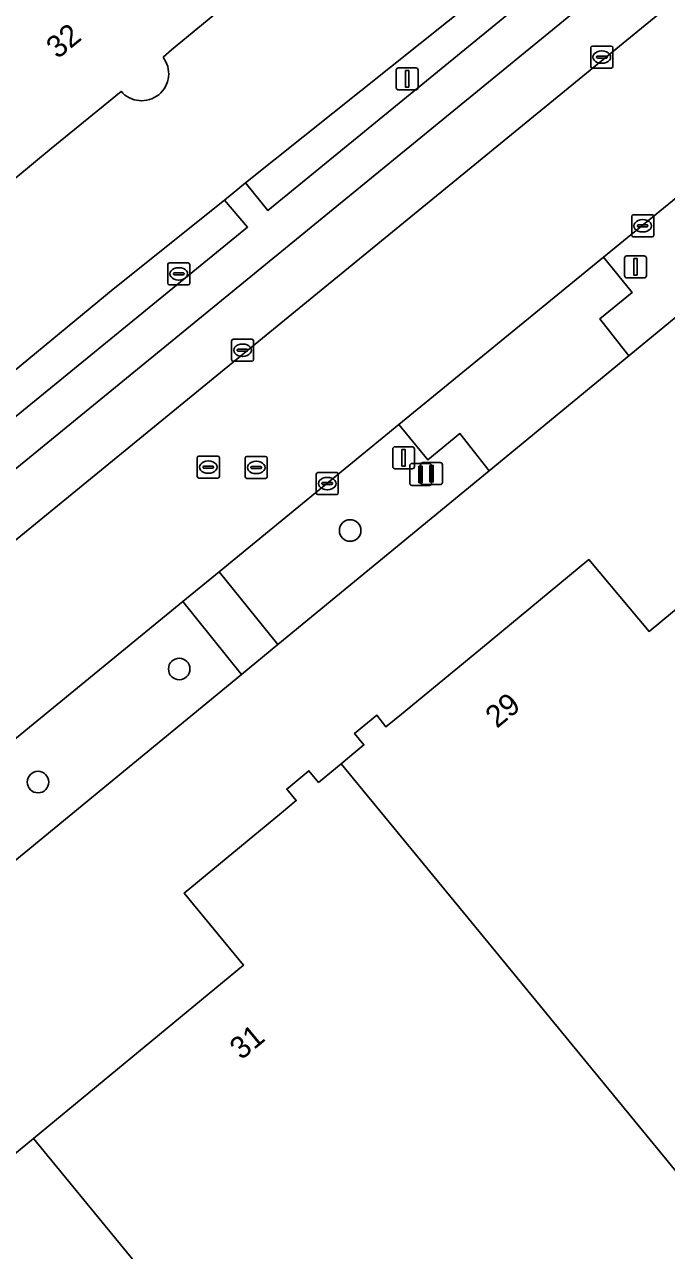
# Model space of a CAD drawing. Extents: x 156702 to 158052, y 387630 to 388992.
# Drawn here: x 156979.3 to 157008.5, y 388172.3 to 388228 of the extents above; entities that cross this region are included whole.
import ezdxf

# ---------------------------------------------------------------- set-up
doc = ezdxf.new("R2010")
doc.units = 0
for name, color, linetype in [('IMGEO_Afsluitpaal', 7, 'Continuous'), ('IMGEO_Berm_groen', 7, 'Continuous'), ('IMGEO_Boom', 7, 'Continuous'), ('IMGEO_Brandkraan', 7, 'Continuous'), ('IMGEO_Erf', 7, 'Continuous'), ('IMGEO_Groenvoorziening', 7, 'Continuous'), ('IMGEO_Hek', 7, 'Continuous'), ('IMGEO_Kolk', 7, 'Continuous'), ('IMGEO_Lichtmast', 7, 'Continuous'), ('IMGEO_Pand', 7, 'Continuous'), ('IMGEO_Pand_nummerreeks', 7, 'Continuous'), ('IMGEO_Parkeervlak_open', 7, 'Continuous'), ('IMGEO_Rijbaan_lokaal_gesloten', 7, 'Continuous'), ('IMGEO_Rijbaan_lokaal_open', 7, 'Continuous'), ('IMGEO_Rioolput', 7, 'Continuous'), ('IMGEO_Verkeersbordpaal', 7, 'Continuous'), ('IMGEO_Voetpad_open', 7, 'Continuous')]:
    doc.layers.add(name, color=color, linetype=linetype)

msp = doc.modelspace()

# ---------------------------------------------------------------- linework, layer by layer
at = {"layer": 'IMGEO_Afsluitpaal'}
for p, q in [((157006.554, 388216.563), (157006.554, 388217.363)), ((157006.554, 388217.363), (157006.554, 388216.563)), ((157006.654, 388217.463), (157007.444, 388217.463)), ((157007.444, 388217.463), (157006.654, 388217.463)), ((157007.544, 388217.363), (157007.544, 388216.563)), ((157007.544, 388216.563), (157007.544, 388217.363)), ((157007.444, 388216.463), (157006.654, 388216.463)), ((157006.654, 388216.463), (157007.444, 388216.463)), ((156996.014, 388207.884), (156996.014, 388208.684)), ((156996.014, 388208.684), (156996.014, 388207.884)), ((156996.114, 388208.784), (156996.904, 388208.784)), ((156996.904, 388208.784), (156996.114, 388208.784)), ((156997.004, 388208.684), (156997.004, 388207.884)), ((156997.004, 388207.884), (156997.004, 388208.684)), ((156996.904, 388207.784), (156996.114, 388207.784)), ((156996.114, 388207.784), (156996.904, 388207.784)), ((156997.285, 388207.165), (156997.285, 388207.965)), ((156997.285, 388207.965), (156997.285, 388207.165)), ((156997.385, 388208.065), (156998.175, 388208.065)), ((156998.175, 388208.065), (156997.385, 388208.065)), ((156998.275, 388207.965), (156998.275, 388207.165)), ((156998.275, 388207.165), (156998.275, 388207.965)), ((156998.175, 388207.065), (156997.385, 388207.065)), ((156997.385, 388207.065), (156998.175, 388207.065))]:
    msp.add_line(p, q, dxfattribs=at)
for points in [[(157006.974, 388217.338), (157007.124, 388217.338), (157007.124, 388216.588), (157006.974, 388216.588), (157006.974, 388217.338)], [(156996.434, 388208.659), (156996.584, 388208.659), (156996.584, 388207.909), (156996.434, 388207.909), (156996.434, 388208.659)], [(156997.705, 388207.94), (156997.855, 388207.94), (156997.855, 388207.19), (156997.705, 388207.19), (156997.705, 388207.94)]]:
    msp.add_lwpolyline(points, dxfattribs=at)
for centre, start, end in [((157006.654, 388217.363), 90, 180), ((157006.654, 388217.363), 90, 180), ((157007.444, 388217.363), 0, 90), ((157007.444, 388217.363), 360, 90), ((157006.654, 388216.563), 180, 270), ((157006.654, 388216.563), 180, 270), ((157007.444, 388216.563), 270, 0), ((157007.444, 388216.563), 270, 0), ((156996.114, 388208.684), 90, 180), ((156996.114, 388208.684), 90, 180), ((156996.904, 388208.684), 0, 90), ((156996.904, 388208.684), 360, 90), ((156996.114, 388207.884), 180, 270), ((156996.114, 388207.884), 180, 270), ((156996.904, 388207.884), 270, 0), ((156996.904, 388207.884), 270, 0), ((156997.385, 388207.965), 90, 180), ((156997.385, 388207.965), 90, 180), ((156998.175, 388207.965), 0, 90), ((156998.175, 388207.965), 360, 90), ((156997.385, 388207.165), 180, 270), ((156997.385, 388207.165), 180, 270), ((156998.175, 388207.165), 270, 0), ((156998.175, 388207.165), 270, 0)]:
    msp.add_arc(centre, 0.1, start, end, dxfattribs=at)
at = {"layer": 'IMGEO_Berm_groen'}
for points in [[(157019.353, 388223.29), (157018.081, 388224.919), (157016.583, 388223.743), (157015.343, 388225.354), (157005.603, 388217.405), (157006.895, 388215.796), (157005.431, 388214.601), (157006.748, 388212.913), (157010.188, 388215.745)], [(157000.402, 388207.692), (156999.068, 388209.388), (156997.608, 388208.193), (156996.295, 388209.802), (156988.13, 388203.105), (156990.785, 388199.795)], [(156989.145, 388198.44), (156986.467, 388201.756), (156976.878, 388193.907), (156978.236, 388192.321), (156976.749, 388191.123), (156978.144, 388189.413)]]:
    msp.add_lwpolyline(points, close=True, dxfattribs=at)
at = {"layer": 'IMGEO_Boom'}
for centre in [(156994.079, 388204.98), (156986.31, 388198.686), (156979.891, 388193.546)]:
    msp.add_circle(centre, 0.489, dxfattribs=at)
at = {"layer": 'IMGEO_Brandkraan'}
for p, q in [((156985.789, 388216.218), (156985.789, 388217.07)), ((156985.864, 388217.144), (156986.716, 388217.144)), ((156986.79, 388217.07), (156986.79, 388216.218)), ((156986.048, 388216.638), (156986.048, 388216.65)), ((156986.486, 388216.601), (156986.088, 388216.601)), ((156986.091, 388216.687), (156986.489, 388216.687)), ((156986.277, 388216.924), (156986.302, 388216.924)), ((156986.532, 388216.65), (156986.532, 388216.638)), ((156986.716, 388216.144), (156985.864, 388216.144)), ((156986.3, 388216.364), (156986.275, 388216.364))]:
    msp.add_line(p, q, dxfattribs=at)
for points in [[(156985.789, 388216.218), (156985.789, 388217.07)], [(156985.864, 388217.144), (156986.716, 388217.144)], [(156986.79, 388217.07), (156986.79, 388216.218)], [(156986.716, 388216.144), (156985.864, 388216.144)]]:
    msp.add_lwpolyline(points, dxfattribs=at)
for centre, radius, start, end in [((156985.866, 388217.068), 0.0765, 91.552, 178.448), ((156985.866, 388217.068), 0.0765, 91.552, 178.448), ((156986.714, 388217.068), 0.0765, 1.552, 88.448), ((156986.714, 388217.068), 0.0765, 1.552, 88.448), ((156986.088, 388216.647), 0.0403, 85.8775, 175.7526), ((156986.085, 388216.637), 0.0366, 178.938, 274.7102), ((156986.489, 388216.644), 0.043, 264.8664, 352.4533), ((156986.493, 388216.649), 0.0386, 1.7309, 96.639), ((156985.866, 388216.22), 0.0765, 181.552, 268.448), ((156985.866, 388216.22), 0.0765, 181.552, 268.448), ((156986.714, 388216.22), 0.0765, 271.552, 358.448), ((156986.714, 388216.22), 0.0765, 271.552, 358.448)]:
    msp.add_arc(centre, radius, start, end, dxfattribs=at)
for centre, major_axis, ratio, start_param, end_param in [((156986.276, 388216.644), (-0.387, 0.002), 0.722429, 4.712389, 7.853982), ((156986.301, 388216.644), (-0.39, 0.002), 0.717154, 1.570796, 4.712389)]:
    msp.add_ellipse(centre, major_axis=major_axis, ratio=ratio, start_param=start_param, end_param=end_param, dxfattribs=at)
at = {"layer": 'IMGEO_Erf'}
for points in [[(157000, 388295.324), (157019.484, 388271.593), (157022.171, 388268.319), (157022.656, 388267.728), (157022.238, 388267.391), (157022.182, 388267.345), (157019.727, 388265.324), (157024.954, 388258.955), (157014.087, 388250), (157000, 388238.392), (156988.351, 388228.793), (156985.964, 388226.83), (156985.576, 388226.496)], [(156904.219, 388206.202), (156931.323, 388173.236), (156933.339, 388174.89), (156934.789, 388176.079), (156942.229, 388182.248), (156965.861, 388201.554), (156983.313, 388215.956), (156988.363, 388220.001), (156989.317, 388220.786), (157030.213, 388253.414), (157032.65, 388255.06), (157032.469, 388255.382), (157038.891, 388259.648), (157039.072, 388259.421), (157039.697, 388259.798), (157039.87, 388259.526)], [(157033.839, 388234.859), (157032.956, 388234.153), (157034.178, 388232.45), (157031.961, 388230.827), (157030.762, 388232.388), (157027.169, 388229.7), (157019.353, 388223.29), (157010.188, 388215.745), (157006.748, 388212.913), (157000.402, 388207.692), (156990.785, 388199.795), (156989.145, 388198.44), (156978.144, 388189.413), (156967.928, 388180.992), (156950.279, 388166.487), (156944.652, 388161.796)], [(156983.663, 388224.94), (156980.491, 388222.335), (156978.06, 388220.344), (156978.012, 388220.304), (156941.415, 388190.276), (156936.176, 388196.64), (156933.645, 388194.564), (156933.233, 388194.214), (156930.06, 388198.078)], [(156963.056, 388163.663), (156979.678, 388177.353), (156989.23, 388185.22), (156986.535, 388188.503), (156990.953, 388192.142), (156991.633, 388192.702), (156991.198, 388193.23), (156992.208, 388194.061), (156992.642, 388193.533), (156992.985, 388193.815), (156993.672, 388194.381), (156994.345, 388194.936), (156994.708, 388195.235), (156994.28, 388195.758), (156995.294, 388196.587), (156995.705, 388196.056), (156996.414, 388196.64), (157000, 388199.593), (157004.934, 388203.657), (157007.67, 388200.391), (157012.983, 388204.785), (157036.896, 388175.64), (157020.3, 388161.977)]]:
    msp.add_lwpolyline(points, dxfattribs=at)
msp.add_arc((156984.598, 388225.745), 1.233, 220.7322, 37.5164, dxfattribs=at)
at = {"layer": 'IMGEO_Groenvoorziening'}
msp.add_lwpolyline([(157029.775, 388251.321), (157031.059, 388252.308), (157030.213, 388253.414), (156989.317, 388220.786), (156990.339, 388219.529), (157017.543, 388241.759)], dxfattribs=at)
msp.add_lwpolyline([(156989.414, 388218.767), (156988.363, 388220.001), (156983.313, 388215.956), (156965.861, 388201.554), (156942.229, 388182.248), (156943.238, 388181.031), (156944.779, 388182.313)], close=True, dxfattribs=at)
at = {"layer": 'IMGEO_Hek'}
for points in [[(156989.317, 388220.786), (157030.213, 388253.414)], [(156988.363, 388220.001), (156989.317, 388220.786)], [(156988.363, 388220.001), (156983.313, 388215.956)], [(156934.789, 388176.079), (156942.229, 388182.248), (156965.861, 388201.554), (156983.313, 388215.956)]]:
    msp.add_lwpolyline(points, dxfattribs=at)
at = {"layer": 'IMGEO_Kolk'}
for p, q in [((157005.019, 388226.071), (157005.019, 388226.923)), ((157005.094, 388226.997), (157005.946, 388226.997)), ((157005.321, 388226.54), (157005.719, 388226.54)), ((157005.507, 388226.777), (157005.532, 388226.777)), ((157006.02, 388226.923), (157006.02, 388226.071)), ((157005.946, 388225.997), (157005.094, 388225.997)), ((157005.278, 388226.491), (157005.278, 388226.503)), ((157005.716, 388226.454), (157005.318, 388226.454)), ((157005.53, 388226.217), (157005.505, 388226.217)), ((157005.762, 388226.503), (157005.762, 388226.491)), ((157006.952, 388219.328), (157007.804, 388219.328)), ((157006.877, 388218.402), (157006.877, 388219.254)), ((157007.136, 388218.822), (157007.136, 388218.834)), ((157007.574, 388218.785), (157007.176, 388218.785)), ((157007.179, 388218.871), (157007.577, 388218.871)), ((157007.365, 388219.108), (157007.39, 388219.108)), ((157007.62, 388218.834), (157007.62, 388218.822)), ((157007.878, 388219.254), (157007.878, 388218.402)), ((157007.804, 388218.328), (157006.952, 388218.328)), ((157007.388, 388218.548), (157007.363, 388218.548)), ((156988.688, 388212.748), (156988.688, 388213.6)), ((156988.763, 388213.674), (156989.615, 388213.674)), ((156988.947, 388213.168), (156988.947, 388213.18)), ((156988.99, 388213.217), (156989.388, 388213.217)), ((156989.176, 388213.454), (156989.201, 388213.454)), ((156989.431, 388213.18), (156989.431, 388213.168)), ((156989.689, 388213.6), (156989.689, 388212.748)), ((156989.615, 388212.674), (156988.763, 388212.674)), ((156989.385, 388213.131), (156988.987, 388213.131)), ((156989.199, 388212.894), (156989.174, 388212.894)), ((156992.615, 388207.613), (156993.467, 388207.613)), ((156992.54, 388206.687), (156992.54, 388207.539)), ((156992.799, 388207.107), (156992.799, 388207.119)), ((156993.237, 388207.07), (156992.839, 388207.07)), ((156992.842, 388207.156), (156993.24, 388207.156)), ((156993.028, 388207.393), (156993.053, 388207.393)), ((156993.283, 388207.119), (156993.283, 388207.107)), ((156993.541, 388207.539), (156993.541, 388206.687)), ((156993.467, 388206.613), (156992.615, 388206.613)), ((156993.051, 388206.833), (156993.026, 388206.833))]:
    msp.add_line(p, q, dxfattribs=at)
for points in [[(157005.019, 388226.071), (157005.019, 388226.923)], [(157005.094, 388226.997), (157005.946, 388226.997)], [(157006.02, 388226.923), (157006.02, 388226.071)], [(157005.946, 388225.997), (157005.094, 388225.997)], [(157006.952, 388219.328), (157007.804, 388219.328)], [(157006.877, 388218.402), (157006.877, 388219.254)], [(157007.878, 388219.254), (157007.878, 388218.402)], [(157007.804, 388218.328), (157006.952, 388218.328)], [(156988.688, 388212.748), (156988.688, 388213.6)], [(156988.763, 388213.674), (156989.615, 388213.674)], [(156989.689, 388213.6), (156989.689, 388212.748)], [(156989.615, 388212.674), (156988.763, 388212.674)], [(156992.615, 388207.613), (156993.467, 388207.613)], [(156992.54, 388206.687), (156992.54, 388207.539)], [(156993.541, 388207.539), (156993.541, 388206.687)], [(156993.467, 388206.613), (156992.615, 388206.613)]]:
    msp.add_lwpolyline(points, dxfattribs=at)
for centre, radius, start, end in [((157005.096, 388226.921), 0.0765, 91.552, 178.448), ((157005.096, 388226.921), 0.0765, 91.552, 178.448), ((157005.318, 388226.5), 0.0403, 85.8775, 175.7526), ((157005.723, 388226.502), 0.0386, 1.7309, 96.639), ((157005.944, 388226.921), 0.0765, 1.552, 88.448), ((157005.944, 388226.921), 0.0765, 1.552, 88.448), ((157005.096, 388226.073), 0.0765, 181.552, 268.448), ((157005.096, 388226.073), 0.0765, 181.552, 268.448), ((157005.315, 388226.49), 0.0366, 178.938, 274.7102), ((157005.719, 388226.497), 0.043, 264.8664, 352.4533), ((157005.944, 388226.073), 0.0765, 271.552, 358.448), ((157005.944, 388226.073), 0.0765, 271.552, 358.448), ((157006.954, 388219.252), 0.0765, 91.552, 178.448), ((157006.954, 388219.252), 0.0765, 91.552, 178.448), ((157007.802, 388219.252), 0.0765, 1.552, 88.448), ((157007.802, 388219.252), 0.0765, 1.552, 88.448), ((157007.176, 388218.831), 0.0403, 85.8775, 175.7526), ((157007.173, 388218.821), 0.0366, 178.938, 274.7102), ((157007.577, 388218.828), 0.043, 264.8664, 352.4533), ((157007.581, 388218.833), 0.0386, 1.7309, 96.639), ((157006.954, 388218.404), 0.0765, 181.552, 268.448), ((157006.954, 388218.404), 0.0765, 181.552, 268.448), ((157007.802, 388218.404), 0.0765, 271.552, 358.448), ((157007.802, 388218.404), 0.0765, 271.552, 358.448), ((156988.765, 388213.598), 0.0765, 91.552, 178.448), ((156988.765, 388213.598), 0.0765, 91.552, 178.448), ((156988.987, 388213.177), 0.0403, 85.8775, 175.7526), ((156988.984, 388213.167), 0.0366, 178.938, 274.7102), ((156989.388, 388213.174), 0.043, 264.8664, 352.4533), ((156989.392, 388213.179), 0.0386, 1.7309, 96.639), ((156989.613, 388213.598), 0.0765, 1.552, 88.448), ((156989.613, 388213.598), 0.0765, 1.552, 88.448), ((156988.765, 388212.75), 0.0765, 181.552, 268.448), ((156988.765, 388212.75), 0.0765, 181.552, 268.448), ((156989.613, 388212.75), 0.0765, 271.552, 358.448), ((156989.613, 388212.75), 0.0765, 271.552, 358.448), ((156992.617, 388207.537), 0.0765, 91.552, 178.448), ((156992.617, 388207.537), 0.0765, 91.552, 178.448), ((156993.465, 388207.537), 0.0765, 1.552, 88.448), ((156993.465, 388207.537), 0.0765, 1.552, 88.448), ((156992.839, 388207.116), 0.0403, 85.8775, 175.7526), ((156992.836, 388207.106), 0.0366, 178.938, 274.7102), ((156993.24, 388207.113), 0.043, 264.8664, 352.4533), ((156993.244, 388207.118), 0.0386, 1.7309, 96.639), ((156992.617, 388206.689), 0.0765, 181.552, 268.448), ((156992.617, 388206.689), 0.0765, 181.552, 268.448), ((156993.465, 388206.689), 0.0765, 271.552, 358.448), ((156993.465, 388206.689), 0.0765, 271.552, 358.448)]:
    msp.add_arc(centre, radius, start, end, dxfattribs=at)
for centre, major_axis, ratio, start_param, end_param in [((157005.506, 388226.497), (-0.387, 0.002), 0.722429, 4.712389, 7.853982), ((157005.531, 388226.497), (-0.39, 0.002), 0.717154, 1.570796, 4.712389), ((157007.364, 388218.828), (-0.387, 0.002), 0.722429, 4.712389, 7.853982), ((157007.389, 388218.828), (-0.39, 0.002), 0.717154, 1.570796, 4.712389), ((156989.175, 388213.174), (-0.387, 0.002), 0.722429, 4.712389, 7.853982), ((156989.2, 388213.174), (-0.39, 0.002), 0.717154, 1.570796, 4.712389), ((156993.027, 388207.113), (-0.387, 0.002), 0.722429, 4.712389, 7.853982), ((156993.052, 388207.113), (-0.39, 0.002), 0.717154, 1.570796, 4.712389)]:
    msp.add_ellipse(centre, major_axis=major_axis, ratio=ratio, start_param=start_param, end_param=end_param, dxfattribs=at)
at = {"layer": 'IMGEO_Lichtmast'}
for p, q in [((156996.275, 388226.006), (156997.065, 388226.006)), ((156997.065, 388226.006), (156996.275, 388226.006)), ((156996.175, 388225.106), (156996.175, 388225.906)), ((156996.175, 388225.906), (156996.175, 388225.106)), ((156997.165, 388225.906), (156997.165, 388225.106)), ((156997.165, 388225.106), (156997.165, 388225.906)), ((156997.065, 388225.006), (156996.275, 388225.006)), ((156996.275, 388225.006), (156997.065, 388225.006))]:
    msp.add_line(p, q, dxfattribs=at)
msp.add_lwpolyline([(156996.595, 388225.881), (156996.745, 388225.881), (156996.745, 388225.131), (156996.595, 388225.131), (156996.595, 388225.881)], dxfattribs=at)
for centre, start, end in [((156996.275, 388225.906), 90, 180), ((156996.275, 388225.906), 90, 180), ((156997.065, 388225.906), 0, 90), ((156997.065, 388225.906), 360, 90), ((156996.275, 388225.106), 180, 270), ((156996.275, 388225.106), 180, 270), ((156997.065, 388225.106), 270, 0), ((156997.065, 388225.106), 270, 0)]:
    msp.add_arc(centre, 0.1, start, end, dxfattribs=at)
at = {"layer": 'IMGEO_Pand'}
for points in [[(156985.576, 388226.496), (156985.964, 388226.83), (156988.351, 388228.793), (157000, 388238.392), (157014.087, 388250), (157024.954, 388258.955)], [(156930.06, 388198.078), (156933.233, 388194.214), (156933.645, 388194.564), (156936.176, 388196.64), (156941.415, 388190.276), (156978.012, 388220.304), (156978.06, 388220.344), (156980.491, 388222.335), (156983.663, 388224.94)]]:
    msp.add_lwpolyline(points, dxfattribs=at)
for points in [[(157000, 388186.68), (157020.3, 388161.977), (157036.896, 388175.64), (157012.983, 388204.785), (157007.67, 388200.391), (157004.934, 388203.657), (157000, 388199.593), (156996.414, 388196.64), (156995.705, 388196.056), (156995.294, 388196.587), (156994.28, 388195.758), (156994.708, 388195.235), (156994.345, 388194.936), (156993.672, 388194.381)], [(156993.672, 388194.381), (156992.985, 388193.815), (156992.642, 388193.533), (156992.208, 388194.061), (156991.198, 388193.23), (156991.633, 388192.702), (156990.953, 388192.142), (156986.535, 388188.503), (156989.23, 388185.22), (156979.678, 388177.353), (157000, 388152.592), (157003.589, 388148.218), (157020.3, 388161.977), (157000, 388186.68)], [(156979.678, 388177.353), (156963.056, 388163.663), (156967.472, 388158.304), (156962.306, 388154.079), (156973.299, 388140.637), (156974.12, 388139.625), (156977.372, 388135.617), (156982.599, 388139.887), (156986.971, 388134.536), (157000, 388145.263), (157003.589, 388148.218), (157000, 388152.592)]]:
    msp.add_lwpolyline(points, close=True, dxfattribs=at)
msp.add_arc((156984.598, 388225.745), 1.233, 220.7322, 37.5164, dxfattribs=at)
at = {"layer": 'IMGEO_Parkeervlak_open'}
for points in [[(157032.362, 388247.883), (157030.887, 388249.913), (157024.565, 388245.043), (157018.331, 388240.059), (156948.653, 388183.095)], [(156947.557, 388178.951), (157019.722, 388237.965)]]:
    msp.add_lwpolyline(points, dxfattribs=at)
at = {"layer": 'IMGEO_Rijbaan_lokaal_gesloten'}
for points in [[(157019.722, 388237.965), (156947.557, 388178.951), (156937.11, 388170.391), (156936.342, 388169.728)], [(156946.742, 388169.256), (156947.504, 388169.869), (156963.742, 388183.161), (156976.878, 388193.907), (156986.467, 388201.756), (156988.13, 388203.105), (156996.295, 388209.802), (157005.603, 388217.405), (157015.343, 388225.354), (157026.109, 388234.117), (157029.774, 388237.027)]]:
    msp.add_lwpolyline(points, dxfattribs=at)
at = {"layer": 'IMGEO_Rijbaan_lokaal_open'}
msp.add_lwpolyline([(156996.295, 388209.802), (156997.608, 388208.193), (156999.068, 388209.388), (157000.402, 388207.692), (157006.748, 388212.913), (157005.431, 388214.601), (157006.895, 388215.796), (157005.603, 388217.405)], close=True, dxfattribs=at)
at = {"layer": 'IMGEO_Rioolput'}
for p, q in [((156987.132, 388207.435), (156987.132, 388208.287)), ((156987.207, 388208.361), (156988.059, 388208.361)), ((156987.62, 388208.141), (156987.645, 388208.141)), ((156988.133, 388208.287), (156988.133, 388207.435)), ((156989.31, 388207.419), (156989.31, 388208.271)), ((156989.385, 388208.345), (156990.237, 388208.345)), ((156989.798, 388208.125), (156989.823, 388208.125)), ((156990.311, 388208.271), (156990.311, 388207.419)), ((156987.391, 388207.855), (156987.391, 388207.867)), ((156987.829, 388207.818), (156987.431, 388207.818)), ((156987.434, 388207.904), (156987.832, 388207.904)), ((156987.643, 388207.581), (156987.618, 388207.581)), ((156987.875, 388207.867), (156987.875, 388207.855)), ((156989.569, 388207.839), (156989.569, 388207.851)), ((156990.007, 388207.802), (156989.609, 388207.802)), ((156989.612, 388207.888), (156990.01, 388207.888)), ((156989.821, 388207.565), (156989.796, 388207.565)), ((156990.053, 388207.851), (156990.053, 388207.839)), ((156988.059, 388207.361), (156987.207, 388207.361)), ((156990.237, 388207.345), (156989.385, 388207.345))]:
    msp.add_line(p, q, dxfattribs=at)
for points in [[(156987.132, 388207.435), (156987.132, 388208.287)], [(156987.207, 388208.361), (156988.059, 388208.361)], [(156988.133, 388208.287), (156988.133, 388207.435)], [(156989.31, 388207.419), (156989.31, 388208.271)], [(156989.385, 388208.345), (156990.237, 388208.345)], [(156990.311, 388208.271), (156990.311, 388207.419)], [(156988.059, 388207.361), (156987.207, 388207.361)], [(156990.237, 388207.345), (156989.385, 388207.345)]]:
    msp.add_lwpolyline(points, dxfattribs=at)
for centre, radius, start, end in [((156987.209, 388208.285), 0.0765, 91.552, 178.448), ((156987.209, 388208.285), 0.0765, 91.552, 178.448), ((156988.057, 388208.285), 0.0765, 1.552, 88.448), ((156988.057, 388208.285), 0.0765, 1.552, 88.448), ((156989.387, 388208.269), 0.0765, 91.552, 178.448), ((156989.387, 388208.269), 0.0765, 91.552, 178.448), ((156990.235, 388208.269), 0.0765, 1.552, 88.448), ((156990.235, 388208.269), 0.0765, 1.552, 88.448), ((156987.431, 388207.864), 0.0403, 85.8775, 175.7526), ((156987.428, 388207.854), 0.0366, 178.938, 274.7102), ((156987.832, 388207.861), 0.043, 264.8664, 352.4533), ((156987.836, 388207.866), 0.0386, 1.7309, 96.639), ((156989.609, 388207.848), 0.0403, 85.8775, 175.7526), ((156989.606, 388207.838), 0.0366, 178.938, 274.7102), ((156990.01, 388207.845), 0.043, 264.8664, 352.4533), ((156990.014, 388207.85), 0.0386, 1.7309, 96.639), ((156987.209, 388207.437), 0.0765, 181.552, 268.448), ((156987.209, 388207.437), 0.0765, 181.552, 268.448), ((156988.057, 388207.437), 0.0765, 271.552, 358.448), ((156988.057, 388207.437), 0.0765, 271.552, 358.448), ((156989.387, 388207.421), 0.0765, 181.552, 268.448), ((156989.387, 388207.421), 0.0765, 181.552, 268.448), ((156990.235, 388207.421), 0.0765, 271.552, 358.448), ((156990.235, 388207.421), 0.0765, 271.552, 358.448)]:
    msp.add_arc(centre, radius, start, end, dxfattribs=at)
for centre, major_axis, ratio, start_param, end_param in [((156987.619, 388207.861), (-0.387, 0.002), 0.722429, 4.712389, 7.853982), ((156987.644, 388207.861), (-0.39, 0.002), 0.717154, 1.570796, 4.712389), ((156989.797, 388207.845), (-0.387, 0.002), 0.722429, 4.712389, 7.853982), ((156989.822, 388207.845), (-0.39, 0.002), 0.717154, 1.570796, 4.712389)]:
    msp.add_ellipse(centre, major_axis=major_axis, ratio=ratio, start_param=start_param, end_param=end_param, dxfattribs=at)
at = {"layer": 'IMGEO_Verkeersbordpaal'}
for p, q in [((156996.788, 388207.128), (156996.788, 388207.928)), ((156996.788, 388207.928), (156996.788, 388207.128)), ((156996.888, 388208.028), (156997.678, 388208.028)), ((156997.678, 388208.028), (156996.888, 388208.028)), ((156997.778, 388207.928), (156997.778, 388207.128)), ((156997.778, 388207.128), (156997.778, 388207.928)), ((156997.678, 388207.028), (156996.888, 388207.028)), ((156996.888, 388207.028), (156997.678, 388207.028))]:
    msp.add_line(p, q, dxfattribs=at)
msp.add_lwpolyline([(156997.208, 388207.903), (156997.358, 388207.903), (156997.358, 388207.153), (156997.208, 388207.153), (156997.208, 388207.903)], dxfattribs=at)
for centre, start, end in [((156996.888, 388207.928), 90, 180), ((156996.888, 388207.928), 90, 180), ((156997.678, 388207.928), 0, 90), ((156997.678, 388207.928), 360, 90), ((156996.888, 388207.128), 180, 270), ((156996.888, 388207.128), 180, 270), ((156997.678, 388207.128), 270, 0), ((156997.678, 388207.128), 270, 0)]:
    msp.add_arc(centre, 0.1, start, end, dxfattribs=at)
at = {"layer": 'IMGEO_Voetpad_open'}
for points in [[(157017.543, 388241.759), (156990.339, 388219.529), (156989.317, 388220.786), (156988.363, 388220.001), (156989.414, 388218.767), (156944.779, 388182.313), (156947.557, 388178.951)], [(156948.653, 388183.095), (157018.331, 388240.059)]]:
    msp.add_lwpolyline(points, dxfattribs=at)
msp.add_lwpolyline([(156986.467, 388201.756), (156989.145, 388198.44), (156990.785, 388199.795), (156988.13, 388203.105)], close=True, dxfattribs=at)

# ---------------------------------------------------------------- texts
at = {"layer": 'IMGEO_Pand_nummerreeks'}
for s, rotation, p in [('32', 39.3106, (156980.784, 388226.382)), ('29', 39.4768, (157000.751, 388195.962)), ('31', 39.4768, (156989.129, 388180.886))]:
    msp.add_text(s, height=1, rotation=rotation, dxfattribs=at).set_placement(p)

doc.saveas('drawing.dxf')
